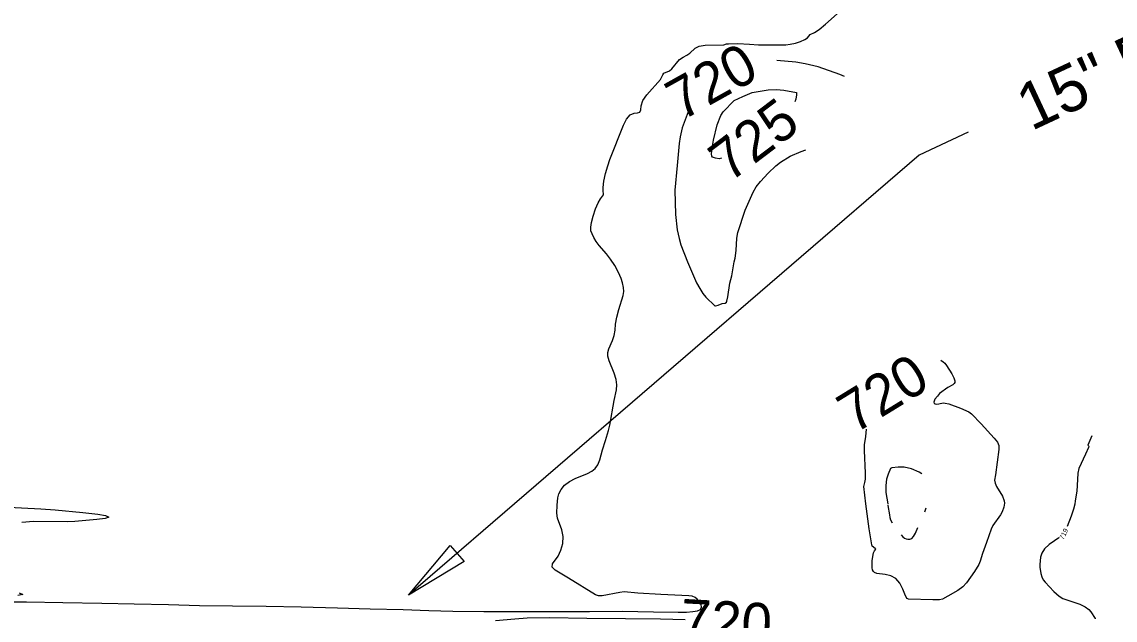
# Model space of a CAD drawing. Extents: x -310467766 to 17062430, y -322263100 to 8322522.
# Drawn here: x 1398585 to 1399466, y 573882 to 574364 of the extents above; entities that cross this region are included whole.
import ezdxf

# ---------------------------------------------------------------- set-up
doc = ezdxf.new("R2010")
doc.units = 0
for name, color, linetype in [('DT_X_Contour_Minor', 7, 'Continuous'), ('Level 19', 7, 'Continuous'), ('Level 40', 7, 'Continuous')]:
    doc.layers.add(name, color=color, linetype=linetype)

msp = doc.modelspace()

# ---------------------------------------------------------------- linework, layer by layer
at = {"layer": 'DT_X_Contour_Minor'}
for points in [[(1399055.63, 574026.89), (1399058.04, 574034.92), (1399059.1, 574039.28), (1399062.69, 574059.22), (1399064.62, 574067.56), (1399064.95, 574071.66), (1399064.37, 574076.15), (1399062.72, 574081.24), (1399058.65, 574091.09), (1399057.65, 574094.75), (1399057.57, 574097.75), (1399058.34, 574100.64), (1399061.43, 574107.48), (1399062.76, 574111.47), (1399063.43, 574115.84), (1399063.88, 574120.72), (1399064.75, 574126.29), (1399066.44, 574132.53), (1399070, 574143.69), (1399070.57, 574146.95), (1399070.1, 574150.28), (1399069.44, 574154.03), (1399068.3, 574157.43), (1399066.11, 574162.28), (1399063.15, 574167.84), (1399059.83, 574173.15), (1399056.54, 574177.45), (1399050.63, 574184.17), (1399048.24, 574187.38), (1399046.31, 574190.51), (1399044.89, 574193.38), (1399044.02, 574195.94), (1399043.81, 574198.77), (1399044.37, 574202.59), (1399045.74, 574207.8), (1399047.65, 574213.51), (1399049.73, 574218.46), (1399051.66, 574221.73), (1399053.99, 574224.81), (1399054.04, 574225.88), (1399053.76, 574227.61), (1399053.75, 574230.8), (1399054.48, 574235.89), (1399055.82, 574242.08), (1399057.5, 574248.24), (1399059.3, 574253.47), (1399070.21, 574281.1), (1399072.71, 574285.93), (1399075.58, 574289.33), (1399078.71, 574290.69), (1399081.56, 574290.99), (1399083.46, 574291.56), (1399084.06, 574293.5), (1399084.38, 574296.73), (1399085.76, 574300.9), (1399089.08, 574305.63), (1399099.96, 574317.8), (1399101.92, 574321.57), (1399102.83, 574323.06), (1399107.2, 574324.9), (1399109.23, 574326.47), (1399115.44, 574334.16), (1399118.24, 574335.99), (1399121.18, 574337.44), (1399123.76, 574339.01), (1399127.9, 574343.11), (1399131.1, 574344.72), (1399135.94, 574345.46), (1399151.17, 574345.96), (1399153.23, 574346.57), (1399154.85, 574346.77), (1399162.26, 574346.82), (1399171.8, 574346.45), (1399179.06, 574345.89), (1399190.04, 574345.86), (1399201.12, 574345.83), (1399204.56, 574346.3), (1399208.71, 574347.24), (1399212.97, 574348.55), (1399216.47, 574350.06), (1399218.6, 574351.61), (1399220.73, 574354.06), (1399224.24, 574355.84), (1399227.86, 574358.23), (1399233.07, 574362.47), (1399247.21, 574375.07)], [(1399248.33, 574320.45), (1399244.46, 574321.84), (1399226.99, 574328), (1399216.69, 574330.47), (1399209.13, 574332.01), (1399193.89, 574333.27)], [(1399159.44, 574300.88), (1399166.27, 574304.29), (1399173.92, 574307.36), (1399186.72, 574309.67), (1399193.41, 574309.81), (1399199.45, 574309.42), (1399209.74, 574307.56), (1399209.71, 574305.65), (1399209.2, 574301.98), (1399208.38, 574299.99)], [(1399149.13, 574254.43), (1399147.21, 574253.97), (1399144.29, 574254.36), (1399142.01, 574255.2), (1399141.34, 574256.21), (1399141.13, 574257.85), (1399141.59, 574262.57), (1399142.87, 574268.99), (1399145.59, 574281.25), (1399148.56, 574288.81), (1399150.53, 574291.73), (1399159.44, 574300.88)], [(1399122.27, 574291.81), (1399117.63, 574279.05), (1399115.91, 574271.71), (1399115.18, 574266.25), (1399113.41, 574248.59), (1399111.71, 574228.59), (1399112.01, 574209.03), (1399113.54, 574196.66), (1399114.96, 574189.73), (1399116.36, 574184.64), (1399121.72, 574170.81), (1399129.14, 574153.98), (1399131.62, 574149.32), (1399134.11, 574145.43), (1399136.65, 574142.53), (1399143.85, 574135.45), (1399144.38, 574135.36), (1399146.39, 574135.98), (1399149.82, 574137.31), (1399152.24, 574137.68), (1399153.27, 574138.44), (1399153.62, 574139.17), (1399154.21, 574142.55), (1399155.83, 574153.82), (1399157.42, 574159.62), (1399159.27, 574170.8), (1399160.17, 574173.77), (1399160.92, 574180.02), (1399161.51, 574190.04), (1399162.38, 574194.42), (1399168.24, 574212.58), (1399174.59, 574227.18), (1399177.16, 574231.34), (1399180.54, 574235.75), (1399186.86, 574242.39), (1399192.97, 574248.38), (1399196.65, 574251.22), (1399204.59, 574256.02), (1399213.3, 574259.92), (1399217.16, 574261.29)], [(1399325.99, 574091.55), (1399327.9, 574090.35), (1399329.05, 574089.21), (1399330.62, 574087.2), (1399334.78, 574080.52), (1399336.42, 574077.29), (1399337.17, 574075.04), (1399337.2, 574073.65), (1399336.81, 574072.81), (1399335.56, 574071.83), (1399331.59, 574069.54), (1399325, 574064.64), (1399323.26, 574062.58), (1399321.02, 574060.16), (1399320.5, 574058.58), (1399320.4, 574057.61), (1399320.61, 574056.79), (1399321.27, 574056.29), (1399322.25, 574056.08), (1399324.46, 574056.28), (1399327.76, 574057.12), (1399329.54, 574057.03), (1399332.5, 574056.3), (1399341.83, 574052.86), (1399348.58, 574049.95), (1399350.62, 574048.39), (1399358.41, 574040.15), (1399368.85, 574028.75), (1399371.63, 574025.39), (1399372.66, 574022.91), (1399372.59, 574019.66), (1399370.11, 573999.21), (1399369.3, 573994.89), (1399369.66, 573992.55), (1399370.86, 573989.85), (1399375.58, 573981.83), (1399377, 573978.27), (1399377.27, 573976.36), (1399376.75, 573973.01), (1399375.38, 573969.42), (1399374.01, 573967.01), (1399367.93, 573958.29), (1399366.49, 573955.39), (1399362.63, 573944.52), (1399359.59, 573935.83), (1399357.66, 573929.43), (1399356.56, 573926.73), (1399353.13, 573921.17), (1399346.73, 573912.06), (1399343.67, 573908.97), (1399339.7, 573905.98), (1399331.68, 573901.2), (1399327.3, 573899.03), (1399324.77, 573898.46), (1399319.42, 573898.47), (1399299.88, 573898.85), (1399298.92, 573899.4), (1399298.06, 573900.49), (1399296.86, 573902.93), (1399295.24, 573907), (1399292.96, 573911.68), (1399289.78, 573915.61), (1399285.59, 573917.82), (1399281.07, 573918.72), (1399274.3, 573919.59), (1399272.57, 573920.32), (1399271.56, 573921.27), (1399270.99, 573922.46), (1399270.72, 573924.14), (1399270.74, 573929.9), (1399271.02, 573933.43), (1399271.58, 573936.31), (1399272.41, 573937.94), (1399273.47, 573939.13), (1399273.03, 573939.75), (1399270.73, 573941.6), (1399270.36, 573942.66), (1399268.22, 573955.62), (1399265.51, 573975.9), (1399263.94, 573989.7), (1399264.7, 573993.04), (1399265.33, 573995.76), (1399265.2, 574000.42), (1399264.32, 574018.76), (1399264.46, 574023.44), (1399265.41, 574029.96), (1399265.99, 574035.96)], [(1399447.72, 574030.6), (1399444.45, 574022.97), (1399445, 574022.55), (1399445.12, 574022.17), (1399444.93, 574021.21), (1399442.65, 574015.92), (1399437.03, 574004.24), (1399436.29, 574000.62), (1399436.01, 573995.41), (1399435.54, 573986.04), (1399434.23, 573978.16), (1399433.94, 573975.58), (1399432.97, 573971.56), (1399431.03, 573965.81), (1399427.71, 573957.55)], [(1398569.38, 573896.87), (1398589.16, 573896.7), (1398618.42, 573896.1), (1398649.87, 573895.64), (1398676.01, 573895.19), (1398703.48, 573894.6), (1398728.59, 573893.88), (1398755.14, 573893.5), (1398782.33, 573893.23), (1398810.51, 573892.74), (1398839.63, 573891.96), (1398866.17, 573891.06), (1398892.65, 573890.55), (1398913.28, 573889.85), (1398932.79, 573889.34), (1398957.72, 573889.07), (1398989.58, 573888.87), (1399017.34, 573888.99), (1399042.81, 573889.06), (1399069.26, 573889.3), (1399094.36, 573888.71), (1399114.22, 573888.39), (1399121, 573888.49), (1399126.08, 573888.84), (1399129.8, 573889.55), (1399132.17, 573890.68), (1399133.12, 573892.33), (1399132.68, 573894.5), (1399131.32, 573896.82), (1399129.59, 573898.83), (1399127.97, 573900.17), (1399125.43, 573901.34), (1399122.8, 573901.71), (1399100.34, 573902.59), (1399081.69, 573903.68), (1399070.77, 573904.72), (1399067.33, 573904.34), (1399052.92, 573901.63), (1399049.98, 573901.53), (1399047.58, 573902.39), (1399026.01, 573915.79), (1399015.25, 573922.18), (1399012.77, 573924.77), (1399012.92, 573927.27), (1399017.53, 573933.7), (1399019.85, 573938.41), (1399021.32, 573943.86), (1399021.57, 573949.51), (1399020.43, 573954.9), (1399017.04, 573964.32), (1399016.44, 573968.21), (1399016.87, 573974.74), (1399017.37, 573980.64), (1399018.24, 573983.8), (1399020.02, 573987.27), (1399022.79, 573990.75), (1399026.61, 573993.86), (1399031.38, 573996.33), (1399041.11, 574000.12), (1399044.72, 574002), (1399047.41, 574004.3), (1399049.45, 574007.34), (1399051.09, 574011.28), (1399053.39, 574019.23), (1399055.63, 574026.89)], [(1399310.59, 574000.04), (1399308.54, 574001.33), (1399302.18, 574003.99), (1399296.38, 574005.21), (1399291.62, 574005.39), (1399286.39, 574004.87), (1399285.47, 574004.23), (1399283.5, 573999.72), (1399282.23, 573995.59), (1399281.49, 573990.52), (1399281.66, 573984.86), (1399283.1, 573975.83)], [(1399283.25, 573974.9), (1399283.31, 573974.5), (1399284.49, 573966.79), (1399284.87, 573964.77), (1399285.49, 573962.97), (1399286.79, 573960.43), (1399286.8, 573960.42)], [(1398569.61, 573973.46), (1398600.81, 573971.62), (1398612.26, 573970.98), (1398634.41, 573968.86), (1398646.62, 573967.39), (1398652.91, 573966.29), (1398655.52, 573965.14), (1398652.46, 573964.07), (1398645.85, 573963.16), (1398628.21, 573961.58), (1398622.26, 573961.36), (1398594.71, 573961.44), (1398585.25, 573960.69)], [(1399312.95, 573969.35), (1399314.24, 573972.67)], [(1399294.01, 573950.83), (1399295.42, 573949.18), (1399296.69, 573948.18), (1399297.92, 573947.61), (1399299.39, 573947.23), (1399301.02, 573947.22), (1399302.6, 573947.91), (1399304.03, 573949.55), (1399305.45, 573952.17), (1399307.44, 573956.57)], [(1399421.16, 573948.35), (1399417.48, 573946.01), (1399413.19, 573942.87), (1399409.5, 573939.36), (1399407.29, 573935.88), (1399406.29, 573932.79), (1399405.59, 573926.82), (1399405.71, 573924.67), (1399406.45, 573919.57), (1399407.22, 573916.84), (1399408.37, 573914.56), (1399409.93, 573912.52), (1399417.07, 573905.13), (1399421.39, 573901.28), (1399424.32, 573899.56), (1399437.86, 573894.76), (1399442.34, 573892.68), (1399445.24, 573890.65), (1399446.91, 573888.7), (1399450.3, 573883.22), (1399450.37, 573883.15)], [(1398583.31, 573904.14), (1398586.13, 573902.66), (1398582.08, 573901.86)], [(1399119.92, 573882.19), (1399099.95, 573882.65), (1399071.85, 573883.17), (1399040.6, 573883.36), (1399010.99, 573883.83), (1398992.57, 573883.47), (1398982.78, 573882.87), (1398967.1, 573881.53)]]:
    msp.add_lwpolyline(points, dxfattribs=at)
at = {"layer": 'Level 40'}
for p, q in [((1399347.92, 574275.32), (1399308.36, 574256.88)), ((1399308.36, 574256.88), (1398897.07, 573902)), ((1398897.07, 573902), (1398930.52, 573942.19)), ((1398930.52, 573942.19), (1398941.74, 573929.19)), ((1398941.74, 573929.19), (1398897.07, 573902))]:
    msp.add_line(p, q, dxfattribs=at)

# ---------------------------------------------------------------- texts
at = {"layer": 'Level 19'}
for s, height, rotation, p in [('720', 33, 29.19793, (1399116.83, 574284.11)), ('725', 33, 37.1735, (1399155.58, 574234.22)), ('720', 33, 31.60435, (1399256.26, 574031.72)), ('719', 4, 63.22016, (1399424.69, 573946.47)), ('720', 33, 356.84958, (1399115.36, 573866.27))]:
    msp.add_text(s, height=height, rotation=rotation, dxfattribs=at).set_placement(p)
at = {"layer": 'Level 40'}
msp.add_text('15" D', height=37.5, rotation=25, dxfattribs=at).set_placement((1399398.79, 574276.15))

doc.saveas('drawing.dxf')
